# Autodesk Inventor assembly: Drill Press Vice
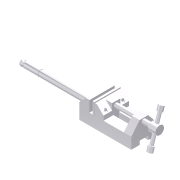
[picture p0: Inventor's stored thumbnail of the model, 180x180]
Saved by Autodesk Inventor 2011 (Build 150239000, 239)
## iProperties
Created: 2009-05
Part Number: Drill Press Vice
Document SubType Name: Assembly
Designer: Sham
Author: Sham
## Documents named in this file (9)
- C:\Users\CADSoft\Desktop\part files\c12-inv-2011-prt\c12-tut03-inv\Drill Press Vice.iam
- C:\Users\CADSoft\Desktop\part files\c12-inv-2011-prt\c12-tut03-inv\Base.ipt
- C:\Users\CADSoft\Desktop\part files\c12-inv-2011-prt\c12-tut03-inv\Safety Handle.ipt
- C:\Users\CADSoft\Desktop\part files\c12-inv-2011-prt\c12-tut03-inv\Jaw Face.ipt
- C:\Users\CADSoft\Desktop\part files\c12-inv-2011-prt\c12-tut03-inv\Movable Jaw.ipt
- C:\Users\CADSoft\Desktop\part files\c12-inv-2011-prt\c12-tut03-inv\Cap Screw.ipt
- C:\Users\CADSoft\Desktop\part files\c12-inv-2011-prt\c12-tut03-inv\Clamp Screw Handle.ipt
- C:\Users\CADSoft\Desktop\part files\c12-inv-2011-prt\c12-tut03-inv\Clamp Screw.ipt
- C:\Users\CADSoft\Desktop\part files\c12-inv-2011-prt\c12-tut03-inv\Handle Stop.ipt
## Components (10 placed, 8 different names)
1. Base:1 — Mate:1, Mate:2, Mate:3, Flush:1
2. Safety Handle:1
3. Jaw Face:1 — Mate:1, Mate:4, Flush:1
4. Movable Jaw:1 — Mate:2, Mate:3, Mate:4, Insert:2, Insert:3, Insert:4
5. Cap Screw:1 — Insert:2
6. Cap Screw:2 — Insert:3
7. Clamp Screw:1 — Insert:4, Mate:6
8. Clamp Screw Handle:1 — Mate:6, Insert:5, Insert:6
9. Handle Stop:1 — Insert:6
10. Handle Stop:2 — Insert:5
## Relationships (11: Mate 5, Insert 5, Flush 1)
- Mate:1: Base:1 ↔ Jaw Face:1
- Mate:2: Base:1 ↔ Movable Jaw:1
- Mate:3: Base:1 ↔ Movable Jaw:1
- Mate:4: Jaw Face:1 ↔ Movable Jaw:1
- Insert:2: Movable Jaw:1 ↔ Cap Screw:1
- Insert:3: Movable Jaw:1 ↔ Cap Screw:2
- Insert:4: Movable Jaw:1 ↔ Clamp Screw:1
- Mate:6: Clamp Screw:1 ↔ Clamp Screw Handle:1
- Insert:5: Clamp Screw Handle:1 ↔ Handle Stop:2
- Insert:6: Clamp Screw Handle:1 ↔ Handle Stop:1
- Flush:1: Base:1 ↔ Jaw Face:1
